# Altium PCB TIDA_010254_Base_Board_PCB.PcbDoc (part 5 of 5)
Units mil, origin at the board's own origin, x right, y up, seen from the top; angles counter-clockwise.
Board outline 3514.38 x 3143.81 mil, 4 copper layers (Top Layer, L2_GND1, L3_PWR1, Bottom Layer), stack 62.715 mil thick; 219 components, 146 nets, 618 pads, 2382 vias.
Unrouted connection lines stored in the file: 2280.
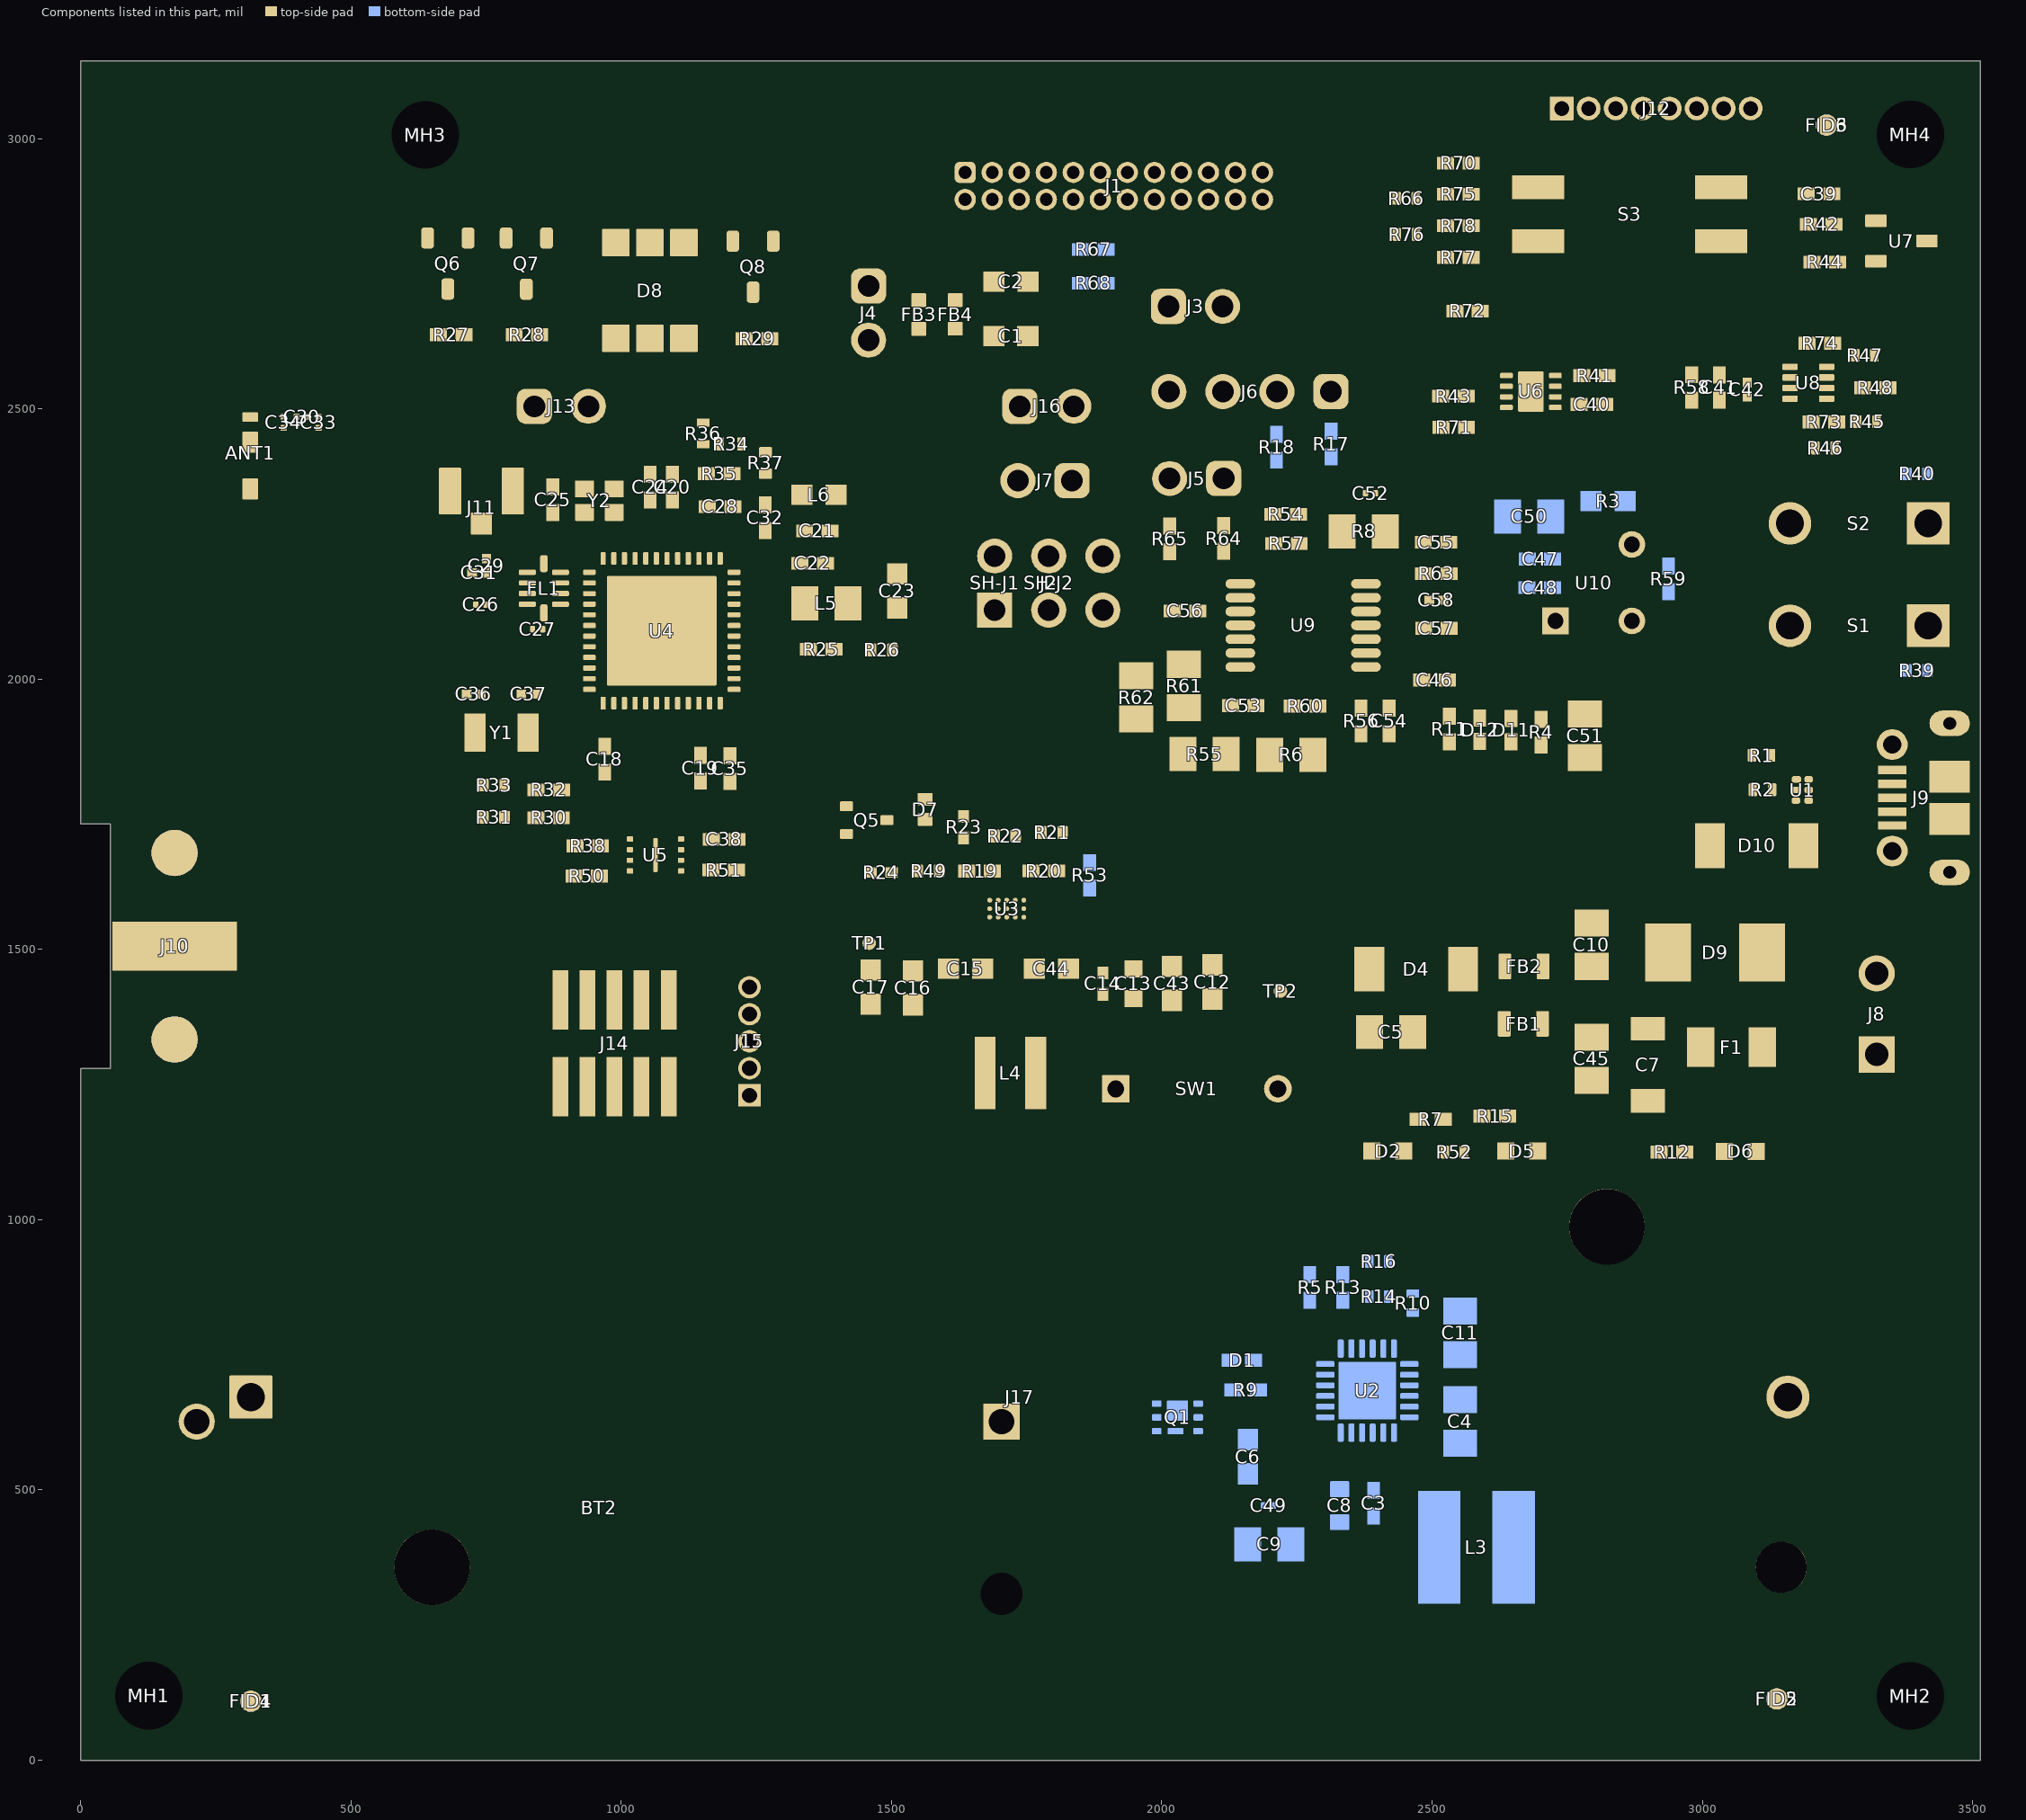
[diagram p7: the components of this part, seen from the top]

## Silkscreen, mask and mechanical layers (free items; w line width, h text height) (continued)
M10 Fab Notes:
  drawing of 251 lines, arcs and shapes, not listed
  text "3" at 3930.48,6750.28 h70
  text "4" at 6437.15,6750.28 h70
  text "5" at 8936.14,6750.28 h70
  text "6" at 11441.14,6750.28 h70
  text "A" at -2210.86,5607.28 h70
  text "A" at 12589.14,5607.28 h70
  text "DESIGN INFORMATION" at 10587.66,5069.96 h60
  text "6.0" at 10982.14,4940.57 h60
  text "MIN. TRACK WIDTH:" at 9943.1,4937.83 h60
  text "MIL" at 11194.1,4937.83 h60
  text "5.0" at 10979.59,4821.18 h60
  text "MIN. CLEARANCE:" at 9943.1,4813.71 h60
  text "MIL" at 11194.1,4813.71 h60
  text "MIN. VIA PAD SIZE:" at 9943.1,4689.58 h60
  text "18" at 10965.78,4682.21 h60
  text "MIL" at 11216.64,4680.78 h60
  text "EXTERNAL" at 11464.24,4562.27 h60
  text "0.127mm (5.0MIL)" at 10638.1,4559.68 h60
  text "MINIMUM ANNULAR RING" at 9613.87,4551.46 h60
  text "PER" at 9813.87,4441.33 h60
  text "IPC-D-275 CLASS 2 LEVEL C" at 10033.87,4441.33 h60
  text "MIL, HOLES" at 11522.1,4340.85 h60
  text "+/-" at 11129.64,4332.27 h60
  text "+/-" at 11983.64,4332.27 h60
  text "REGISTRATION TOLERANCES:" at 9613.87,4331.2 h60
  text "METAL" at 10813.64,4331.2 h60
  text "5" at 11389.84,4331.21 h60
  text "3" at 12222.84,4331.21 h60
  text "MIL" at 12339.1,4331.2 h60
  text "HOLE SIZE TOLERANCE (UNLESS OTHERWISE SPECIFIED):" at 9613.87,4232.89 h60
  text "+/-" at 11983.64,4230.02 h60
  text "3" at 12222.84,4228.95 h60
  text "MIL" at 12339.1,4228.95 h60
  text "MATERIAL:" at 9539.1,4091.3 h60
  text "FR-4 High Tg" at 10525.54,3962.78 h60
  text "X" at 11267.64,3957.78 h60
  text "REFER STACK-UP" at 11768.49,3957.19 h55
  text "FR-408" at 9960.1,3950.27 h60
  text "OTHER" at 11448.1,3950.27 h60
  text "62 MIL (1.6mm) +/-10%" at 10280.2,3807.24 h60
  text "X" at 10157.81,3804.5 h60
  text "THICKNESS:" at 9613.87,3799.02 h60
  text "OTHER" at 11565.1,3799.02 h60
  text "TOLERANCE:" at 9613.87,3660.71 h60
  text "X" at 10462.1,3660.71 h60
  text "ANSI IPC-6012 TYPE 3 CLASS 2" at 10640.12,3660.71 h60
  text "OTHER +/-" at 10640.1,3516.52 h60
  text "BOW & TWIST:" at 9613.87,3371.33 h60
  text "X" at 10462.1,3371.33 h60
  text "ANSI IPC-6012 TYPE 3 CLASS 2" at 10640.12,3371.33 h60
  text "B" at -2210.86,3227.28 h70
  text "B" at 12589.14,3227.28 h70
  text "NOTES:" at 3770.56,3224.66 h60
  text "OTHER +/-" at 10640.1,3224.63 h60
  text "DRILLING:" at 9539.1,3094.01 h60
  text "1. BOARD SHALL MEET THE REQUIREMENTS OF UL-796E WITH FLAMMABILITY RATING OF MINIMUM 94V-0. UL LOGO," at 3761.15,3036.35 h60
  text "NC_DRILL FILES" at 11300.1,2988.82 h60
  text "REFERENCE:" at 9613.87,2984.89 h60
  text "X" at 10271.1,2984.79 h60
  text "AS SHOWN" at 10449.1,2984.89 h60
  text "X" at 11172.1,2984.89 h60
  text "MANUFACTURER'S IDENTIFICATION AND DATE CODE LETTER SHALL BE RENDERED IN SILKSCREEN." at 3869.43,2932.78 h60
  text "OTHER" at 11598.1,2842.64 h60
  text "PTH COPPER THICKNESS:" at 9613.54,2839.11 h60
  text "X" at 10752.78,2839.11 h60
  text "20-30 um" at 10880.78,2839.11 h60
  text "2. VENDOR MAY ADJUST SOLDERMASK WHEREVER SOLDERMASK PADS ARE THE SAME SIZE (1:1) AS PER THE MANUFACTURING" at 3763.5,2829.21 h60
  text "CAPABILITIES AND ALL OTHER SOLDER MASK PADS SHALL NOT BE MODIFIED, PROVIDED NO ADJACENT COPPER IS EXPOSED AND" at 3876.49,2718.58 h60
  text "BOARD FINISH:" at 9539.1,2691.51 h60
  text "NO CONFLICT IS PRODUCED WITH ANY STATED \"VIA TENTING/COVERING\" REQUIREMENTS." at 3829.41,2605.59 h60
  text "SILKSCREEN:" at 9694.32,2581.38 h60
  text "X" at 10652.1,2581.38 h60
  text "TOP" at 10769.1,2581.38 h60
  text "X" at 11162.1,2581.38 h60
  text "BOTTOM" at 11280.1,2581.38 h60
  text "3. MANUFACTURER'S IDENTIFICATION,DATECODE LETTER SHALL BE SILKSCREENED ON SOLDER SIDE OF THE BOARD." at 3756.44,2509.08 h60
  text "SILKSCREEN COLOR:" at 9694.32,2426.19 h60
  text "X" at 10651.1,2426.19 h60
  text "WHITE" at 10769.1,2426.19 h60
  text "OTHER" at 11280.1,2426.19 h60
  text "4. TRACE WIDTH SHOULD BE ACCURATELY ETCHED. MAX TOLERANCE +/- 1 MIL." at 3751.73,2400.8 h60
  text "5. LAYER TO LAYER REGISTRATION SHALL BE WITHIN +/-2 MIL." at 3761.15,2290.17 h60
  text "GREEN" at 10900.1,2282.75 h60
  text "X" at 11374.1,2282.75 h60
  text "OTHER" at 11518.1,2282.75 h60
  text "RED" at 11890.64,2282.75 h60
  text "SOLDER RESIST COLOR:" at 9694.32,2275.88 h60
  text "6. REFER IMPEDANCE TABLE FOR IMPEDANCE CONTROL TRACES ON LAYER 1, 4." at 3761.15,2163.06 h60
  text "MATTE" at 10900.1,2128.49 h60
  text "SEMI-GLOSS" at 11517.64,2127.86 h60
  text "X" at 11373.7,2125.8 h60
  text "7. FOR ACCURACY OF THE ANTENNA DIMENSION, NEED TO BE MEASURE THE  ANTENNA DIMENSIONS ON ONE BOARD" at 3763.98,2043.95 h60
  text "IMMERSION GOLD (ENIG)" at 10600.1,1955.72 h60
  text "X" at 10422.28,1950.04 h60
  text "ENEPIG" at 11937.64,1948.5 h60
  text "SURFACE FINISH:" at 9539.1,1947.5 h60
  text "8. ALL VIAS ARE TENTED ON BOTH SIDES UNLESS OTHERWISE SOLDER MASK OPENED IN GERBER." at 3762.31,1920.5 h60
  text "IMM. TIN/SILVER OR EQUIV" at 9868.64,1810.19 h60
  text "OTHER" at 11300.1,1806.25 h60
  text "9. VIA HOLE OFFSET SHALL BE WITHIN 1MILS OF ITS ORIGINAL LOCATION" at 3761.48,1803.72 h60
  text "ARRAY/PANEL:" at 9539.1,1650.87 h60
  text "CUT AND TRIM PER M1 BOARD OUTLINE" at 10600.1,1642.65 h60
  text "N.C. ROUTE" at 10600.1,1506.68 h60
  text "V. SCORE" at 11466.1,1506.68 h60
  text "X" at 11283.1,1500.74 h60
  text "CERTIFICATION:" at 9539.1,1377.56 h60
  text "MATERIALS AND WORKMANSHIP FOR ALL PCBS" at 10264.1,1377.56 h60
  text "TO MEET OR EXCEED THE REQUIREMENTS OF:" at 10264.1,1283.49 h60
  text "X" at 9901.61,1154.86 h60
  text "ANSI IPC-A-600F CLASS ->" at 10029.6,1154.86 h60
  text "X" at 11677.61,1154.86 h60
  text "2" at 11787.6,1154.86 h60
  text "1" at 11472.6,1153.37 h60
  text "3" at 12141.6,1153.37 h60
  text "X" at 10713.61,1007.18 h60
  text "RoHS" at 10841.6,1007.18 h60
  text "OTHER" at 11486,1007.18 h60
  text "PER ORDER" at 11883.06,1007.18 h60
  text "ALL BOARDS MUST MEET OR EXCEED UL94-V0 REQUIREMENTS." at 9566.64,853.35 h60
  text "C" at -2210.86,852.28 h70
  text "C" at 12589.14,852.28 h70
  text "PCB MUST BEAR THE UL94V-0 UL REGISTERED MATERIAL ID NUMBER" at 9566.64,737.29 h60
  text "ADDITIONAL REQUIREMENTS:" at 9539.1,567.86 h60
  text "MICROSECTION:" at 9613.87,460.74 h60
  text "YES" at 10519.6,460.74 h60
  text "REQUIRED" at 11381.1,316.4 h60
  text "BARE BOARD ELEC. TEST:" at 9613.87,313.55 h60
  text "NONE" at 10919.6,313.55 h60
  text "X" at 11263.1,313.55 h60
  text "PER ORDER" at 11973.1,313.55 h60
  text "XX MIL VIAS REQUIRE NON-CONDUCTIVE FILL AND PLANARIZE" at 9797.64,167.78 h59
  text "XX MIL VIAS REQUIRE CONDUCTIVE FILL AND PLANARIZE" at 9788.64,8.78 h60
  text "OUTER XX MIL TRACES REQUIRE 50 OHM SINGLE-ENDED IMPEDANCE" at 9783.79,-134.11 h58
  text "LAYER 1 & 6 (INNER LAYERS) XX MIL WIDE, XX MIL SPACE / TRACES REQUIRE 100 OHM DIFFERENTIAL IMPEDANCE" at 9822.64,-384.22 h60
  text "PROJECT TITLE:" at 9549.14,-1008.72 h45
  text ".PRJ_Title" at 9599.14,-1142.04 h70
  text "DESIGNED FOR:" at 9549.14,-1309.72 h45
  text ".PRJ_Customer" at 9599.14,-1449.72 h70
  text "D" at -2210.86,-1517.72 h70
  text "D" at 12589.14,-1517.72 h70
  text "FILE NAME:" at 9549.14,-1609.72 h45
  text ".PCB_File_Name_No_Path" at 9599.14,-1729.72 h70
  text "Texas Instruments (TI) and/or its licensors do not warrant the accuracy or completeness of this specification" at 4579.64,-1891.55 h45
  text "ENGINEER:" at 9549.14,-1899.72 h45
  text "LAYOUT BY:" at 11054.14,-1899.72 h45
  text "or any information contained therein. TI and/or its licensors do not warrant that this design will meet" at 4534.65,-2004.22 h45
  text ".PRJ_Engineer" at 9599.14,-2054.71 h70
  text ".PCB_Layout" at 11104.64,-2054.71 h70
  text "the specifications, will be suitable for your application or fit for any particular purpose, or will operate in" at 4534.65,-2116.88 h45
  text ".Layer_Name" at -1219.95,-2145.34 h60
  text "ALTIUM DESIGNER VERSION:" at 11054.14,-2209.72 h45
  text "an implementation. TI and/or its licensors do not warrant that the design is production worthy. You should" at 4534.65,-2229.55 h45
  text "completely validate and test your design implementation to confirm the system functionality for your application." at 4579.64,-2342.22 h45
  text ".print_Scale" at 9599.14,-2343.04 h70
  text ".Application_BuildNumber" at 11104.64,-2343.04 h70
  text "3" at 3930.48,-2549.72 h70
  text "4" at 6437.15,-2549.72 h70
  text "5" at 8936.14,-2549.72 h70
  text "6" at 11290.32,-2560.07 h70
M11 Gerber Information:
  lines w10: -2086.36,-2216.38 4513.64,-2216.38 ; -2086.36,-2013.05 4515.64,-2013.05 ; -2086.36,-1809.72 -2086.36,-2419.72 1918.64,-2419.72 4515.64,-2419.72 4515.64,-1809.72 -2085.86,-1809.72 -2085.86,-2419.72 -510.36,-2419.72 ; 378.64,-2419.72 378.64,-1809.72 ; 1645.64,-2013.05 1645.64,-1809.72 ; 2485.64,-2013.05 2485.64,-1809.72 ; 3107.64,-2426.22 3107.64,-2223.38
  text "ALL ARTWORK VIEWED FROM TOP SIDE" at -2022.86,-1941.88 h60
  text "BOARD #:" at 453.64,-1941.88 h60
  text ".PRJ_Number" at 999.14,-1941.88 h60
  text "REV:" at 1843.64,-1941.88 h60
  text ".PCB_Rev" at 2135.14,-1941.88 h60
  text "SVN REV:" at 2681.64,-1941.88 h60
  text ".VersionControl_RevNumber" at 3187.64,-1941.88 h60
  text "LAYER NAME =" at -2022.86,-2144.71 h60
  text "TID #:" at 453.64,-2145.22 h60
  text ".TID" at 999.14,-2145.22 h60
  text "PLOT NAME =" at -2022.86,-2350.55 h60
  text ".plot_File_Name" at -1217.36,-2350.55 h60
  text "GENERATED    :" at 455.64,-2350.55 h60
  text ".Print_Date" at 1325.14,-2350.55 h60
  text ".Print_Time" at 2054.14,-2350.55 h60
  text "TEXAS INSTRUMENTS" at 3318.64,-2350.55 h60
M12 Stackup:
  drawing of 344 lines, arcs and shapes, not listed
  text "NOTE :" at 5325.63,5829.19 h60
  text "1. THIS IS AN IMPEDANCE CONTROLLED BOARD." at 5509.14,5724.17 h60
  text "2. EXTERNAL LAYER CU THICKNESSES ARE FINISHED THICKNESS AFTER PLATING." at 5509.14,5626.3 h60
  text "6" at 7393.27,5463.6 h60
  text "IMPEDANCE TABLE :" at 6236.88,5448.22 h80
  text "LAYER" at 5735.13,5338.87 h70
  text "TRACE WIDTH" at 6022.33,5338.03 h70
  text "SPACING" at 6507.33,5338.03 h70
  text "IMPEDANCE +/- 10%" at 6842.33,5338.03 h70
  text "REFERENCE LAYER" at 7567.33,5338.03 h70
  text "TOP" at 5802.21,5179.89 h70
  text "7.0 MILS" at 6087.21,5174.89 h65
  text "10 MILS" at 6542.21,5174.89 h65
  text "50 OHM" at 6962.21,5174.89 h65
  text "LAYER-2 (GND LAYER)" at 7527.21,5174.89 h65
  text "LAYER" at 5734.16,4961.23 h70
  text "TRACE WIDTH" at 6021.36,4960.39 h70
  text "SPACING" at 6506.36,4960.39 h70
  text "IMPEDANCE +/- 10%" at 6841.36,4960.39 h70
  text "REFERENCE LAYER" at 7566.36,4960.39 h70
  text "LAYER-2" at 7607.67,4792.56 h65
  text "TOP" at 5753.34,4790.03 h70
  text "5.8 MILS" at 6113.14,4780.02 h65
  text "5.2 MILS" at 6546.4,4778.34 h65
  text "90 OHM" at 7007.61,4778.36 h65
  text "90 OHM" at 7003.67,4613.18 h65
  text "LAYER-3" at 7600.4,4610.9 h65
  text "5.8 MILS" at 6104.71,4609.75 h65
  text "5.2 MILS" at 6551.46,4609.75 h65
  text "BOTTOM" at 5709.07,4588.6 h60
  text "LAYER STACK-UP :" at 3876.02,1125.29 h80
  text "Layer" at 3952.63,884.67 h60
  text "Name" at 4362.55,884.67 h60
  text "Material" at 5292.29,884.67 h60
  text "Thickness" at 6282.02,884.67 h60
  text "Constant" at 6931.85,884.67 h60
  text "Board Layer Stack" at 7501.71,884.67 h60
  text "Top Overlay" at 4362.55,764.67 h60
  text "Top Solder" at 4362.55,644.67 h60
  text "Solder Resist" at 5292.29,644.67 h60
  text "0.80mil" at 6282.02,644.67 h60
  text "4" at 6931.85,644.67 h60
  text "1" at 3952.63,524.67 h60
  text "Top Layer" at 4362.55,524.67 h60
  text "1.61mil" at 6282.02,524.67 h60
  text "Dielectric 1" at 4362.55,404.67 h60
  text "FR-4 2116(54%)" at 5292.29,404.67 h60
  text "4.37mil" at 6282.02,404.67 h60
  text "4" at 6931.85,404.67 h60
  text "2" at 3952.63,284.67 h60
  text "L2_GND1" at 4362.55,284.67 h60
  text "1.18mil" at 6282.02,284.67 h60
  text "Dielectric 2" at 4362.55,164.67 h60
  text "KB-6160 1.3mm" at 5292.29,164.67 h60
  text "48.39mil" at 6282.02,164.67 h60
  text "4" at 6931.85,164.67 h60
  text "3" at 3952.63,44.67 h60
  text "L3_PWR1" at 4362.55,44.67 h60
  text "1.18mil" at 6282.02,44.67 h60
  text "Dielectric 3" at 4362.55,-75.33 h60
  text "FR-4 2116(54%)" at 5292.29,-75.33 h60
  text "4.37mil" at 6282.02,-75.33 h60
  text "4" at 6931.85,-75.33 h60
  text "4" at 3952.63,-195.33 h60
  text "Bottom Layer" at 4362.55,-195.33 h60
  text "1.61mil" at 6282.02,-195.33 h60
  text "Bottom Solder" at 4362.55,-315.33 h60
  text "Solder Resist" at 5292.29,-315.33 h60
  text "0.80mil" at 6282.02,-315.33 h60
  text "4" at 6931.85,-315.33 h60
  text "Bottom Overlay" at 4362.55,-435.33 h60
  text ".Layer_Name" at -1217.36,-2144.71 h60
M13 Component Bodies Top:
  text ".Layer_Name" at -1217.36,-2144.71 h60
M14 Component Bodies Bottom:
  text ".Layer_Name" at -1217.36,-2144.71 h60
M15 Courtyards Top:
  text ".Layer_Name" at -1217.36,-2144.71 h60
M16 Courtyards Bottom:
  text ".Layer_Name" at -1217.36,-2144.71 h60
Drill Drawing:
  drawing of 178 lines, arcs and shapes, not listed
  text "Symbol" at -1759.6,6674.82 h72
  text "Count" at -1253.72,6674.82 h72
  text "Hole Size" at -593.9,6674.82 h72
  text "Plated" at 555.77,6674.82 h72
  text "Hole Tolerance (+)" at 1061.64,6674.82 h72
  text "Hole Tolerance (-)" at 2395.25,6674.82 h72
  text "Hole Length" at 3728.86,6674.82 h72
  text "1" at -1253.72,6524.82 h60
  text "77.95mil (1.980mm)" at -593.9,6524.82 h60
  text "NPTH" at 555.77,6524.82 h60
  text "-" at 3728.86,6524.82 h60
  text "C" at -1788.69,6514.83 h66.67
  text "1" at -1253.72,6374.82 h60
  text "94.09mil (2.390mm)" at -593.9,6374.82 h60
  text "NPTH" at 555.77,6374.82 h60
  text "-" at 3728.86,6374.82 h60
  text "2" at -1253.72,6224.82 h60
  text "31.50mil (0.800mm)" at -593.9,6224.82 h60
  text "PTH" at 555.77,6224.82 h60
  text "-" at 3728.86,6224.82 h60
  text "D" at -1788.69,6214.83 h66.67
  text "2" at -1253.72,6074.82 h60
  text "33.47mil (0.850mm)" at -593.9,6074.82 h60
  text "NPTH" at 555.77,6074.82 h60
  text "-" at 3728.86,6074.82 h60
  text "2" at -1253.72,5924.82 h60
  text "43.31mil (1.100mm)" at -593.9,5924.82 h60
  text "PTH" at 555.77,5924.82 h60
  text "-" at 3728.86,5924.82 h60
  text "2" at -1253.72,5774.82 h60
  text "46.85mil (1.190mm)" at -593.9,5774.82 h60
  text "PTH" at 555.77,5774.82 h60
  text "-" at 3728.86,5774.82 h60
  text "2" at -1253.72,5624.82 h60
  text "51.97mil (1.320mm)" at -593.9,5624.82 h60
  text "PTH" at 555.77,5624.82 h60
  text "-" at 3728.86,5624.82 h60
  text "2" at -1253.72,5474.82 h60
  text "139.76mil (3.550mm)" at -593.9,5474.82 h60
  text "NPTH" at 555.77,5474.82 h60
  text "-" at 3728.86,5474.82 h60
  text "3" at -1253.72,5324.82 h60
  text "29.53mil (0.750mm)" at -593.9,5324.82 h60
  text "PTH" at 555.77,5324.82 h60
  text "-" at 3728.86,5324.82 h60
  text "4" at -1253.72,5174.82 h60
  text "23.62mil (0.600mm)" at -593.9,5174.82 h60
  text "PTH" at 555.77,5174.82 h60
  text "51.18mil (1.300mm)" at 3728.86,5174.82 h60
  text "4" at -1253.72,5024.82 h60
  text "33.47mil (0.850mm)" at -593.9,5024.82 h60
  text "PTH" at 555.77,5024.82 h60
  text "-" at 3728.86,5024.82 h60
  text "A" at -1788.69,5014.83 h66.67
  text "4" at -1253.72,4874.82 h60
  text "51.18mil (1.300mm)" at -593.9,4874.82 h60
  text "PTH" at 555.77,4874.82 h60
  text "-" at 3728.86,4874.82 h60
  text "4" at -1253.72,4724.82 h60
  text "125.00mil (3.175mm)" at -593.9,4724.82 h60
  text "NPTH" at 555.77,4724.82 h60
  text "-" at 3728.86,4724.82 h60
  text "B" at -1788.69,4714.83 h66.67
  text "9" at -1253.72,4574.82 h60
  text "11.81mil (0.300mm)" at -593.9,4574.82 h60
  text "PTH" at 555.77,4574.82 h60
  text "-" at 3728.86,4574.82 h60
  text "21" at -1253.72,4424.82 h60
  text "7.87mil (0.200mm)" at -593.9,4424.82 h60
  text "PTH" at 555.77,4424.82 h60
  text "-" at 3728.86,4424.82 h60
  text "37" at -1253.72,4274.82 h60
  text "27.56mil (0.700mm)" at -593.9,4274.82 h60
  text "PTH" at 555.77,4274.82 h60
  text "-" at 3728.86,4274.82 h60
  text "48" at -1253.72,4124.82 h60
  text "40.00mil (1.016mm)" at -593.9,4124.82 h60
  text "PTH" at 555.77,4124.82 h60
  text "-" at 3728.86,4124.82 h60
  text "62" at -1253.72,3974.82 h60
  text "8.00mil (0.203mm)" at -593.9,3974.82 h60
  text "PTH" at 555.77,3974.82 h60
  text "-" at 3728.86,3974.82 h60
  text "E" at -1788.69,3964.83 h66.67
  text "2488" at -1253.72,3824.82 h60
  text "8.00mil (0.203mm)" at -593.9,3824.82 h60
  text "PTH" at 555.77,3824.82 h60
  text "3.00mil (0.076mm)" at 1061.64,3824.82 h60
  text "3.00mil (0.076mm)" at 2395.25,3824.82 h60
  text "-" at 3728.86,3824.82 h60
  text "2698 Total" at -1253.72,3674.82 h60
  text "Slot definitions :" at -1759.6,3529.85 h60
  text "Routed Path Length" at -726.91,3529.85 h60
  text "= Calculated from tool start centre position to tool end centre position." at 375.76,3529.85 h60
  text "Hole Length" at -726.91,3429.87 h60
  text "= Routed Path Length + Tool Size = Slot length as defined in the PCB layout" at -34.11,3429.87 h60
  text ".Layer_Name" at -1217.36,-2144.71 h60
M17 Embedded Cavity:
  text ".Layer_Name" at -1217.36,-2144.71 h60
M18 Embedded Assembly:
  text ".Layer_Name" at -1217.36,-2144.71 h60
M19 Embedded Keepout:
  text ".Layer_Name" at -1217.36,-2144.71 h60
mmwave module:
  drawing of 147 lines, arcs and shapes, not listed
AOP module:
  lines w2: 2294.68,3590.24 2349.01,3612.29 2349.01,3967.02 2274.78,3967.02 2096.27,4041.96 2096.27,4528.8 2274.78,4603.71 2349.01,4603.71 2349.01,5032 1449.01,5032 1449.01,4603.71 1523.24,4603.71 1698.01,4525.26 1698.01,4045.11 1523.24,3967.02 1449.01,3967.02 1449.01,2819.29 2349.01,2819.29 2349.01,3266.29 2294.85,3289.71 ; 2294.82,3289.67 2294.82,3590.5
  lines w10: 1445.27,3645.41 2354.27,3645.41

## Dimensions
0,3143.81 to 0,0 on M2 Board Dimensions
54.85,1732.58 to 0,1279.47 on M2 Board Dimensions
0,1279.47 to 3514.35,3143.81 on M2 Board Dimensions
0,1279.47 to 0,0 on M2 Board Dimensions
297.78,3029.96 to 327.74,3038.12 on M2 Board Dimensions
-84.08,2059.61 to -86.31,1936.62 on M2 Board Dimensions
0,1279.47 to 55.69,3098.93 on M2 Board Dimensions
2212.04,2846.81 to 2342.83,2827.2 on M16 Courtyards Bottom
1612.04,2846.81 to 1484.61,2827.2 on M16 Courtyards Bottom
1484.61,4459.95 to 1484.61,2827.2 on M16 Courtyards Bottom
1484.61,4459.95 to 2342.83,4459.95 on M16 Courtyards Bottom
